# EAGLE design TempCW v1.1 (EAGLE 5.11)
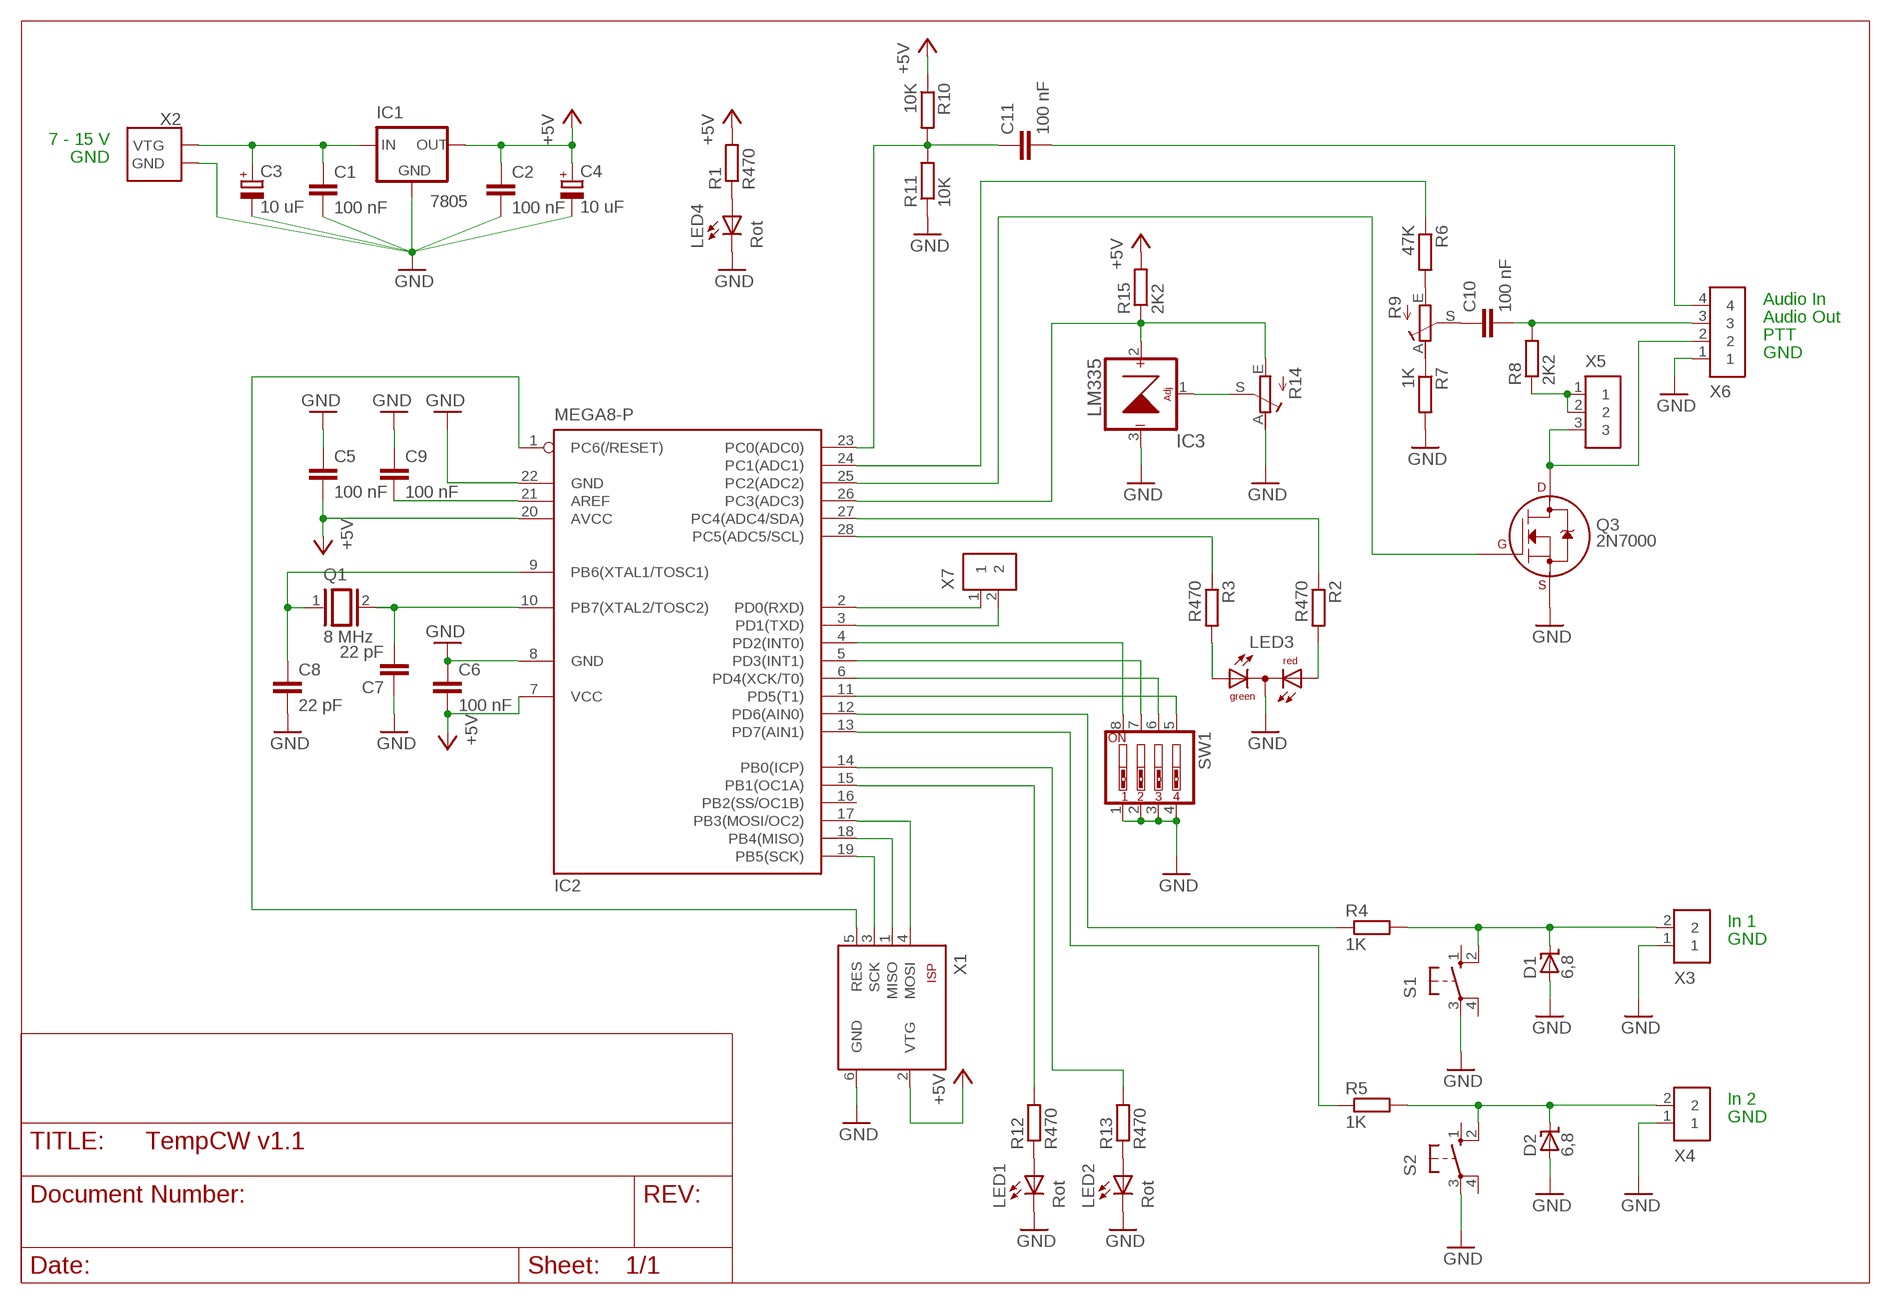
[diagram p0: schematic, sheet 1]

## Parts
C1  100 nF  CAPACITOR  [C]
C2  100 nF  CAPACITOR  [C]
C3  10 uF  CAPACITOR_POL6  [E2,5-6]
C4  10 uF  CAPACITOR_POL6  [E2,5-6]
C5  100 nF  CAPACITOR  [C]
C6  100 nF  CAPACITOR  [C]
C7  22 pF  CAPACITOR  [C]
C8  22 pF  CAPACITOR  [C]
C9  100 nF  CAPACITOR  [C]
C10  100 nF  CAPACITOR  [C]
C11  100 nF  CAPACITOR  [C]
D1  6,8  DIODE_SUPPRESSOR  [PRINT]
D2  6,8  DIODE_SUPPRESSOR  [PRINT]
IC1  7805  V-REG_B  [78XXS]
IC2  MEGA8-P  [DIL28-3]
IC3  LM335  [TO92-123]
LED1  Rot  LED_5MM  [5MM]
LED2  Rot  LED_5MM  [5MM]
LED3  Rot Grün  DUO_5  [DUO]
LED4  Rot  LED_5MM  [5MM]
Q1  8 MHz  CRYSTAL  [CRYSTAL]
Q3  2N7000  2N7000_TO92  [TO-92]
R1  R470  RESISTOR  [RESISTOR]
R2  R470  RESISTOR  [RESISTOR]
R3  R470  RESISTOR  [RESISTOR]
R4  1K  RESISTOR  [RESISTOR]
R5  1K  RESISTOR  [RESISTOR]
R6  47K  RESISTOR  [RESISTOR]
R7  1K  RESISTOR  [RESISTOR]
R8  2K2  RESISTOR  [RESISTOR]
R9  10K  TRIMM_SMALL  [RTRIM_SMALL]
R10  10K  RESISTOR  [RESISTOR]
R11  10K  RESISTOR  [RESISTOR]
R12  R470  RESISTOR  [RESISTOR]
R13  R470  RESISTOR  [RESISTOR]
R14  10K  TRIMM_SMALL  [RTRIM_SMALL]
R15  2K2  RESISTOR  [RESISTOR]
S1  S1  10-XX  [B3F-10XX]
S2  S2  10-XX  [B3F-10XX]
SW1  Dip4  DIP4  [DIP4]
X1  ISP  ISP_H6  [HARTING6]
X2  Power  POWER_W2  [WAGO2]
X3  2PIN  2PIN_W2  [WAGO2]
X4  2PIN  2PIN_W2  [WAGO2]
X5  3PIN  [PINHEAD_1X3]
X6  4PIN  4PIN_W4  [WAGO4]
X7  2PIN  [PINHEAD_1X2]

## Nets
+5V: C2.1 C4.+ C5.2 C6.2 IC1.OUT IC2.7(VCC) IC2.20(AVCC) R1.2 R10.1 R15.2 X1.2(VTG)
GND: C1.2 C2.2 C3.- C4.- C5.1 C6.1 C7.1 C8.2 C9.1 D1.A D2.A IC1.GND IC2.8(GND) IC2.22(GND) IC3.3(MINUS) LED1.K(C) LED2.K(C) LED3.K(C) LED4.K(C) Q3.1(S) R7.2 R11.1 R14.A S1.3(P) S2.3(P) SW1.1 SW1.2 SW1.3 SW1.4 X1.6(GND) X2.2(GND) X3.1 X4.1 X6.1
N$1: C8.1 IC2.9(PB6(XTAL1/TOSC1)) Q1.1
N$2: LED4.A R1.1
N$3: C7.2 IC2.10(PB7(XTAL2/TOSC2)) Q1.2
N$4: IC2.19(PB5(SCK)) X1.3(SCK)
N$5: C9.2 IC2.21(AREF)
N$6: IC2.18(PB4(MISO)) X1.1(MISO)
N$7: IC2.17(PB3(MOSI/OC2)) X1.4(MOSI)
N$8: IC2.1(PC6(/RESET)) X1.5(RES)
N$9: IC2.3(PD1(TXD)) X7.2
N$10: IC2.2(PD0(RXD)) X7.1
N$11: IC2.4(PD2(INT0)) SW1.8
N$12: IC2.5(PD3(INT1)) SW1.7
N$13: IC2.6(PD4(XCK/T0)) SW1.6
N$14: IC2.11(PD5(T1)) SW1.5
N$15: LED3.AR R2.2
N$16: LED3.AG R3.2
N$17: IC2.27(PC4(ADC4/SDA)) R2.1
N$18: IC2.28(PC5(ADC5/SCL)) R3.1
N$19: C1.1 C3.+ IC1.IN X2.1(VTG)
N$20: R6.2 R9.E
N$21: R7.1 R9.A
N$22: C10.2 R8.2 X6.3
N$23: R8.1 X5.1 X5.2
N$24: Q3.3(D) X5.3 X6.2
N$25: D1.C R4.2 S1.2(S1) X3.2
N$26: IC2.26(PC3(ADC3)) IC3.2(PLUS) R14.E R15.1
N$27: IC3.1(ADJ) R14.S
N$28: IC2.24(PC1(ADC1)) R6.1
N$29: IC2.25(PC2(ADC2)) Q3.2(G)
N$30: C11.1 IC2.23(PC0(ADC0)) R10.2 R11.2
N$32: C11.2 X6.4
N$33: D2.C R5.2 S2.2(S1) X4.2
N$34: LED1.A R12.1
N$35: LED2.A R13.1
N$36: IC2.15(PB1(OC1A)) R12.2
N$37: IC2.14(PB0(ICP)) R13.2
N$38: IC2.12(PD6(AIN0)) R4.1
N$39: IC2.13(PD7(AIN1)) R5.1
N$43: C10.1 R9.S
Unconnected: IC2.16(PB2(SS/OC1B)) S1.1(S) S1.4(P1) S2.1(S) S2.4(P1)

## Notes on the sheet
- 7 - 15 V
- GND
- Audio In
- Audio Out
- PTT
- GND
- In 1
- GND
- In 2
- GND

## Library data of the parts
C1 C2 C5-C11 = Capacitors:CAPACITOR: CAPACITOR, European symbol
C3 C4 = Capacitors:CAPACITOR_POL: POLARIZED CAPACITOR, European symbol
D1 D2 = Diodes:DIODE_SUPPRESSOR: Suppressor diode
IC1 = Voltage-Regulators:V-REG: VOLTAGE REGULATOR
IC2 = __atmel:MEGA8-P: MICROCONTROLLER 8 Kbytes FLASH, 1 kbytes SRAM, 512 bytes EEPROM, USART, 4-channel 10 bit ADC, 2-channel 8 bit ADC Pin compatible with Atmega48, ATMega88, ATMega168 Source: avr.lbr; OC_FARNELL: unknown; OC_NEWARK: unknown
IC3 = __lm335:LM335
LED1 LED2 LED4 = LEDs:LED: LED
LED3 = LEDs:DUO_5: DUO LED 2 colors, 5 mm, round
Q1 = Crystals:CRYSTAL: CRYSTAL
Q3 = __transistors:2N700*: 2N7000, 2N7002, NDS7002A N-channel enhancement mode MOSFET
R1-R8 R10-R13 R15 = Resistors:RESISTOR: RESISTOR, European symbol
R9 R14 = Resistors:TRIMM: Trimm resistor
S1 S2 = Switches:10-XX: OMRON SWITCH
SW1 = Switches:DIP4: DIP SWITCH
X1 = Connectors:ISP: HARTING
X2 = Connectors:POWER: WAGO SREW CLAMP
X3 X4 X7 = Connectors:2PIN
X5 = Connectors:3PIN
X6 = Connectors:4PIN

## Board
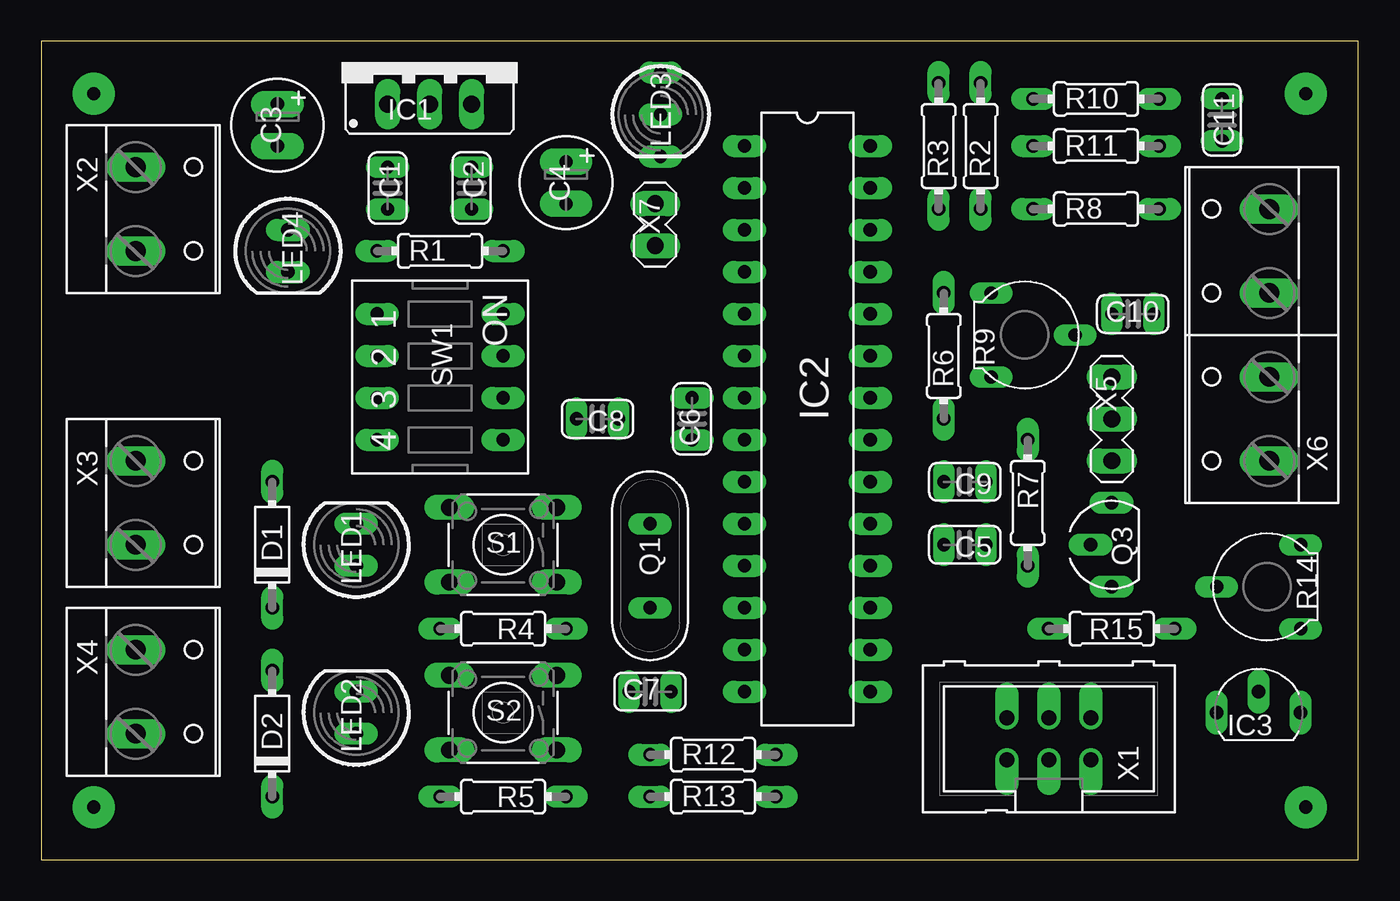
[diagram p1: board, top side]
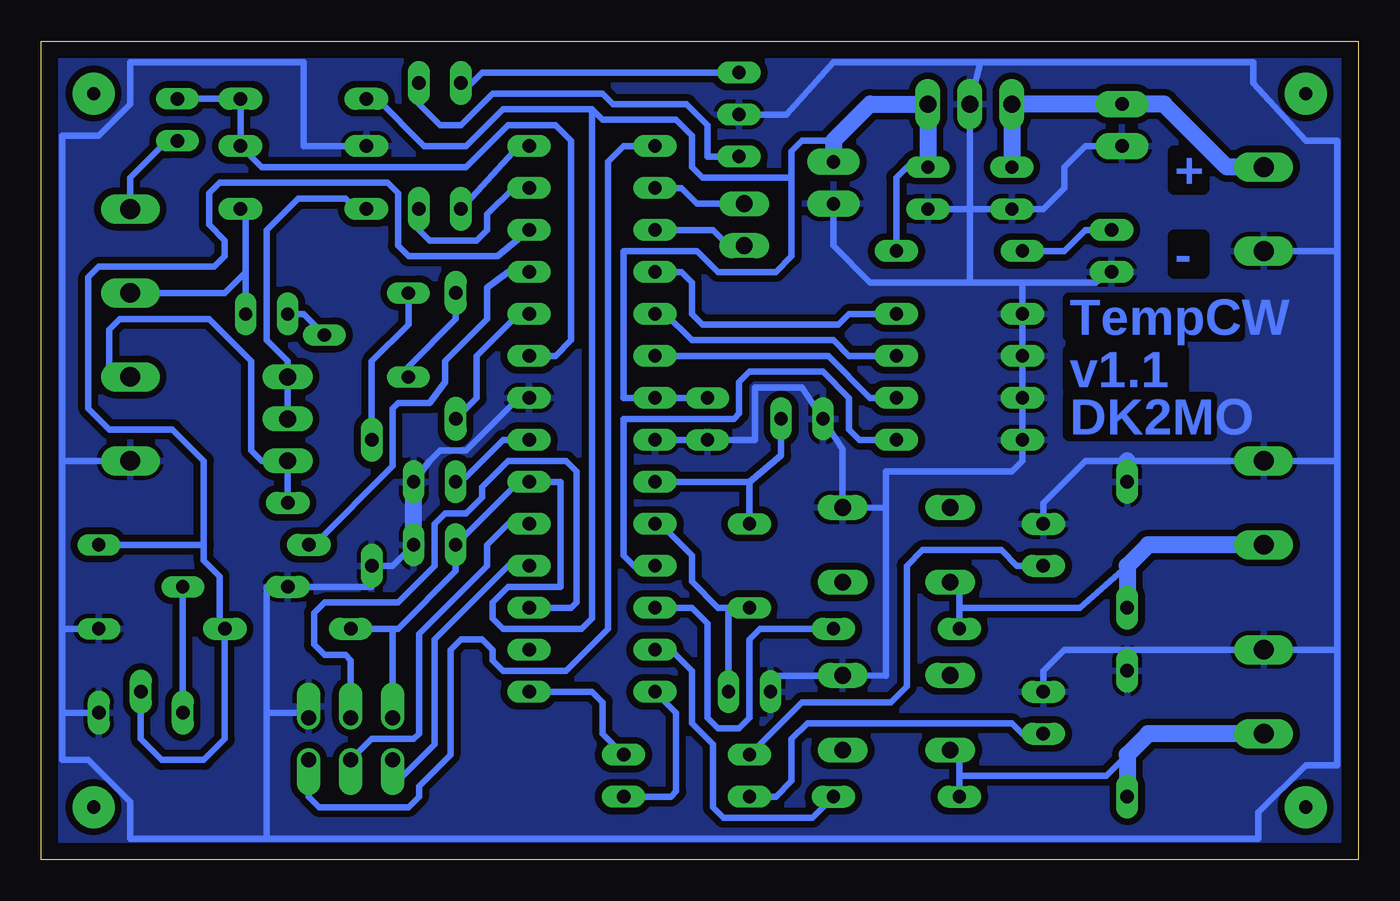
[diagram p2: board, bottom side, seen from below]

Size 79.68 x 49.52 mm. Coordinates in mm from the lower left corner, seen from the top.
Outline: 0,0 79.68,0 79.68,49.52 0,49.52 0,0
Copper layers (1*16): Top 0.035mm / dielectric 1.5mm / Bottom 0.035mm
Design rules "default": minimum track width 10mil, minimum drill 24mil, track to track 8mil, track to pad 8mil, pad to pad 8mil, via to via 8mil, smd to smd 8mil, copper to edge 40mil, drill to drill 8mil, minimum pad ring 10mil, minimum via ring 8mil, stop-mask expansion 4mil, vias tented up to drill 0mil, thermal gap 10mil

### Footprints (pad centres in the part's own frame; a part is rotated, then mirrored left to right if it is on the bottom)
C = drill 0.8 long: 1 -1.27,0; 2 1.27,0
E2,5-6 = drill 0.813 pad 1.6 long: + -1.27,0; - 1.27,0
PRINT = drill 0.813 long: A 3.81,0; C -3.81,0
78XXS = drill 1.016 long: GND 0,-2.54; IN -2.54,-2.54; OUT 2.54,-2.54
DIL28-3 = drill 0.813 long: 1 -16.51,-3.81; 2 -13.97,-3.81; 3 -11.43,-3.81; 4 -8.89,-3.81; 5 -6.35,-3.81; 6 -3.81,-3.81; 7 -1.27,-3.81; 8 1.27,-3.81; 9 3.81,-3.81; 10 6.35,-3.81; 11 8.89,-3.81; 12 11.43,-3.81; 13 13.97,-3.81; 14 16.51,-3.81; 15 16.51,3.81; 16 13.97,3.81; 17 11.43,3.81; 18 8.89,3.81; 19 6.35,3.81; 20 3.81,3.81; 21 1.27,3.81; 22 -1.27,3.81; 23 -3.81,3.81; 24 -6.35,3.81; 25 -8.89,3.81; 26 -11.43,3.81; 27 -13.97,3.81; 28 -16.51,3.81
TO92-123 = drill 0.813 long: 1 -2.54,0; 2 0,1.27; 3 2.54,0
5MM = drill 0.813 long: A -1.27,0; K 1.27,0
DUO = drill 0.813 long: AG -2.54,0; AR 2.54,0; K 0,0
CRYSTAL = drill 0.8 long: 1 -2.54,0; 2 2.54,0
TO-92 = drill 0.813 long: 1 -2.54,0; 2 0,1.27; 3 2.54,0
RESISTOR = drill 0.813 long: 1 -3.81,0; 2 3.81,0
RTRIM_SMALL = drill 0.8 long: A 2.54,0; E -2.54,0; S 0,-5.08
B3F-10XX = drill 1.016 long: 1 -3.251,2.261; 2 3.251,2.261; 3 -3.251,-2.261; 4 3.251,-2.261
DIP4 = drill 0.813 long: 1 -3.81,-3.81; 2 -1.27,-3.81; 3 1.27,-3.81; 4 3.81,-3.81; 5 3.81,3.81; 6 1.27,3.81; 7 -1.27,3.81; 8 -3.81,3.81
HARTING6 = drill 0.914 offset: 1 -2.54,-1.27; 2 -2.54,1.27; 3 0,-1.27; 4 0,1.27; 5 2.54,-1.27; 6 2.54,1.27
WAGO2 = drill 1.194 long: 1 -2.54,-0.635; 2 2.54,-0.635
PINHEAD_1X3 = drill 1.016 long: 1 -2.54,0; 2 0,0; 3 2.54,0
WAGO4 = drill 1.194 long: 1 -7.62,-0.635; 2 -2.54,-0.635; 3 2.54,-0.635; 4 7.62,-0.635
PINHEAD_1X2 = drill 1.016 long: 1 -1.27,0; 2 1.27,0

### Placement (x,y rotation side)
C1  20.95,40.64 270 top
C2  26.04,40.64 270 top
C3  14.29,44.45 270 top
C4  31.75,40.96 270 top
C5  55.88,19.05 180 top
C6  39.37,26.67 90 top
C7  36.83,10.16 0 top
C8  33.66,26.67 180 top
C9  55.88,22.86 180 top
C10  66.04,33.02 0 top
C11  71.44,44.77 270 top
D1  13.97,19.05 90 top
D2  13.97,7.62 90 top
IC1  23.5,48.26 0 top
IC2  46.35,26.67 270 top
IC3  73.66,8.89 0 top
LED1  19.05,19.05 90 top
LED2  19.05,8.89 90 top
LED3  37.47,45.09 270 top
LED4  14.92,36.83 270 top
Q1  36.83,17.78 270 top
Q3  64.77,19.05 90 top
R1  24.13,36.83 0 top
R2  56.83,43.18 90 top
R3  54.29,43.18 90 top
R4  27.94,13.97 180 top
R5  27.94,3.81 180 top
R6  54.61,30.48 90 top
R7  59.69,21.59 270 top
R8  63.82,39.37 0 top
R9  57.47,31.75 90 top
R10  63.82,46.04 0 top
R11  63.82,43.18 0 top
R12  40.64,6.35 0 top
R13  40.64,3.81 0 top
R14  76.2,16.51 270 top
R15  64.77,13.97 180 top
S1  27.94,19.05 180 top
S2  27.94,8.89 180 top
SW1  24.13,29.21 270 top
X1  60.96,7.3 0 top
X2  6.35,39.37 270 top
X3  6.35,21.59 270 top
X4  6.35,10.16 270 top
X5  64.77,26.67 270 top
X6  73.66,31.75 90 top
X7  37.15,38.42 270 top

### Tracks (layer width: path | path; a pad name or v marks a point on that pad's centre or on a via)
+5V
  Bottom 0.406: C6.2 IC2.7 44.45,27.94 44.45,36.83 40.01,36.83 38.73,35.56 35.24,35.56 34.29,36.51 34.29,41.27 | 58.42,13.97 X1.2 | 50.8,22.86 C5.2 54.61,17.46 58.1,13.97 58.42,13.97 | C2.1 27.3,41.91 27.94,41.27 R1.2 | R10.1 59.37,46.04 56.52,43.18 53.98,43.18 51.75,45.4 46.35,45.4 | 34.29,41.27 39.69,41.27 40.32,41.91 40.32,43.81 41.27,44.77 45.72,44.77 46.35,45.4 | IC2.20 48.26,22.86 48.26,16.51 51.44,16.51 52.39,15.56 52.39,14.61 51.75,13.97 46.99,13.97 46.35,14.61 46.35,45.4 | 58.42,13.97 R15.2 | 34.29,41.27 34.29,42.86 33.66,43.5 31.75,43.5
  Bottom 1.016: C2.1 IC1.OUT 29.53,45.72 31.75,43.5 C4.+ | IC2.20 50.8,22.86
GND
  Bottom 0.406: 23.5,39.37 C1.2 19.05,39.37 17.78,40.64 17.78,41.91 16.51,43.18 C3.- | 23.5,39.37 C2.2 | 1.27,36.83 X2.2 | 1.27,24.13 1.27,36.83 | 1.27,24.13 X3.1 13.97,24.13 16.51,24.13 19.05,21.59 LED1.K | 1.27,12.7 1.27,24.13 | 1.27,12.7 X4.1 13.97,12.7 | 78.42,24.13 X6.1 | 23.5,39.37 IC1.GND 22.86,48.26 | 66.04,8.89 63.5,8.89 X1.6 | 66.04,1.27 66.04,8.89 | 35.56,10.79 35.24,11.11 31.11,11.11 S2.3 28.57,11.11 28.57,21.27 | 13.97,12.7 D2.A | 13.97,12.7 17.78,12.7 19.05,11.43 LED2.K | IC2.8 C6.1 36.51,25.4 36.51,28.57 33.66,28.57 C8.2 31.19,24.84 S1.3 28.57,21.27 | 78.42,13.97 78.42,24.13 | R11.1 63.82,43.18 63.82,48.26 74.3,48.26 74.3,45.72 76.2,43.81 78.42,43.81 78.42,24.13 | C4.- 31.75,37.15 29.53,34.92 23.5,34.92 | 23.5,39.37 23.5,34.92 | 23.5,34.92 20.32,34.92 | 28.57,21.27 28.57,23.5 20.95,23.5 20.32,24.13 SW1.4 SW1.3 SW1.2 SW1.1 20.32,34.92 | IC2.22 50.8,27.94 53.98,24.77 55.56,24.77 56.2,24.13 C9.1 | 66.04,8.89 66.04,16.51 Q3.1 59.69,16.51 R7.2 58.42,17.78 C5.1 | 78.42,13.97 R14.A | 1.27,36.83 1.27,43.5 3.17,43.5 6.35,46.99 6.35,48.26 22.86,48.26 | 1.27,12.7 1.27,5.71 3.17,5.71 6.03,2.86 6.03,1.27 66.04,1.27 | 66.04,1.27 74.3,1.27 74.3,3.49 76.83,6.03 78.42,6.03 78.42,8.89 | 78.42,8.89 78.42,13.97 | LED4.K 15.88,34.92 20.32,34.92 | 78.42,8.89 IC3.3 | LED3.K 34.61,45.09 31.75,48.26 22.86,48.26
  Bottom 1.016: C5.1 C9.1 | 35.56,10.79 C7.1 | 13.97,24.13 D1.A
  pour Bottom (isolate 0.406): 0,49.53 79.69,49.53 79.69,0 0,0
N$1
  Bottom 0.406: 36.83,22.86 IC2.9 | Q1.1 36.83,22.86 | C8.1 34.92,24.45 36.83,22.86
N$2
  Bottom 0.406: LED4.A 16.51,38.1 17.78,36.83 R1.1
N$3
  Bottom 0.406: C7.2 38.1,15.24 | 38.1,15.24 Q1.2 | 38.1,15.24 38.73,15.24 40.32,16.83 40.32,18.41 41.91,20 42.23,20 IC2.10
N$4
  Bottom 0.406: IC2.19 51.44,20.32 52.7,19.05 52.7,17.78 56.83,13.65 56.83,7.62 57.15,7.3 59.69,7.3 X1.3
N$5
  Bottom 0.406: IC2.21 51.75,25.4 54.29,22.86 C9.2
N$6
  Bottom 0.406: IC2.18 51.44,17.78 55.88,13.34 55.88,6.99 58.42,4.45 X1.1
N$7
  Bottom 0.406: IC2.17 47.62,15.24 47.31,15.56 47.31,23.5 47.94,24.13 51.44,24.13 53.02,22.54 53.02,21.91 53.98,20.95 55.24,20.95 55.88,20.32 55.88,17.78 58.1,15.56 62.55,15.56 63.18,14.92 63.18,13.02 62.55,12.38 61.28,12.38 60.96,12.06 X1.4
N$8
  Bottom 0.406: IC2.1 44.45,43.18 45.4,42.23 45.4,13.97 47.94,11.43 51.75,11.43 52.39,12.06 52.39,12.7 53.02,13.34 54.29,13.34 54.93,12.7 54.93,6.35 56.83,4.45 56.83,3.81 57.47,3.17 62.87,3.17 63.5,3.81 X1.5
N$9
  Bottom 0.406: IC2.3 39.05,38.1 38.1,37.15 X7.2
N$10
  Bottom 0.406: IC2.2 40.96,40.64 40.01,39.69 X7.1
N$11
  Bottom 0.406: IC2.4 40.96,35.56 40.32,34.92 40.32,33.02 39.69,32.38 31.43,32.38 30.8,33.02 SW1.8
N$12
  Bottom 0.406: SW1.7 30.8,30.48 31.75,31.43 40.32,31.43 41.91,33.02 IC2.5
N$13
  Bottom 0.406: SW1.6 29.53,27.94 32.07,30.48 IC2.6
N$14
  Bottom 0.406: IC2.11 43.81,17.78 44.45,18.41 44.45,26.67 37.78,26.67 37.47,26.99 37.47,28.89 36.83,29.53 32.38,29.53 30.8,27.94 30.8,26.04 30.16,25.4 SW1.5
N$15
  Bottom 0.406: R2.2 56.83,45.72 55.56,44.45 54.29,44.45 52.39,46.35 45.72,46.35 45.09,45.72 40.64,45.72 39.37,44.45 39.37,42.55 LED3.AR
N$16
  Bottom 0.406: R3.2 53.66,46.99 53.02,47.62 LED3.AG
N$17
  Bottom 0.406: IC2.27 51.12,40.64 52.7,39.05 52.7,38.1 53.34,37.47 56.2,37.47 56.83,38.1 R2.1
N$18
  Bottom 0.406: R3.1 50.8,43.18 IC2.28
N$19
  Bottom 1.016: X2.1 7.94,41.91 11.75,45.72 C3.+ IC1.IN C1.1
N$20
  Bottom 0.406: R6.2 54.61,32.7 57.47,29.84 R9.E
N$21
  Bottom 0.406: R9.A 57.47,32.38 59.69,30.16 R7.1
N$22
  Bottom 0.406: R8.2 67.31,39.37 67.31,35.56 | C10.2 67.31,35.56 | X6.3 68.58,34.29 67.31,35.56
N$23
  Bottom 0.406: X5.2 X5.1 64.77,30.16 66.04,31.43 66.04,38.1 64.14,40.01 61.28,40.01 60.64,39.37 R8.1
N$24
  Bottom 0.406: Q3.3 X5.3 66.36,24.13 66.99,24.77 66.99,30.16 69.53,32.7 74.93,32.7 75.56,32.07 75.56,29.53 74.61,29.53 X6.2
N$25
  Bottom 0.406: 13.97,17.78 16.83,15.24 24.13,15.24 R4.2 24.13,16.83 24.17,16.79 S1.2
  Bottom 1.016: X3.2 12.7,19.05 13.97,17.78 D1.C
N$26
  Bottom 0.406: 69.85,19.05 R14.E | IC2.26 52.07,36.51 57.47,36.51 58.1,37.15 58.1,40.32 58.74,40.96 68.9,40.96 69.53,40.32 69.53,38.42 68.58,37.47 68.58,36.51 69.22,35.88 76.2,35.88 76.83,35.24 76.83,27.3 75.56,26.04 71.75,26.04 69.85,24.13 69.85,19.05 | IC3.2 73.66,7.3 72.39,6.03 69.85,6.03 68.58,7.3 R15.1 68.9,14.29 68.9,17.14 69.85,18.1 69.85,19.05
N$27
  Bottom 0.406: IC3.1 R14.S
N$28
  Bottom 0.406: R6.1 53.34,27.94 53.34,30.48 50.8,33.02 IC2.24
N$29
  Bottom 0.406: IC2.25 51.44,35.56 52.7,34.61 52.7,32.7 55.24,30.16 55.24,28.89 56.2,27.62 58.1,27.62 58.42,27.3 58.42,23.81 63.18,19.05 Q3.2
N$30
  Bottom 0.406: C11.1 R10.2 R11.2 66.36,41.91 53.98,41.91 51.44,44.45 48.58,44.45 47.62,43.5 47.62,31.43 48.58,30.48 IC2.23
N$31  (via drill 0.8 pad 2.54)
  other vias: 3.17,46.35
N$32
  Bottom 0.406: C11.2 72.07,43.5 72.39,43.18 74.3,41.27 X6.4 74.93,39.37
N$33
  Bottom 0.406: 24.13,5.08 24.13,6.35 S2.2 | 13.97,6.35 15.24,5.08 24.13,5.08 | 24.13,5.08 R5.2
  Bottom 1.016: X4.2 12.7,7.62 13.97,6.35 D2.C
N$34
  Bottom 0.406: LED1.A 20.64,17.78 21.59,18.73 26.35,18.73 27.3,17.78 27.3,10.48 28.26,9.53 33.66,9.53 R12.1
N$35
  Bottom 0.406: LED2.A 20.32,7.62 20.95,8.26 33.34,8.26 34.29,7.3 34.29,4.76 35.24,3.81 R13.1
N$36
  Bottom 0.406: R12.2 45.72,7.62 45.72,9.53 46.35,10.16 IC2.15
N$37
  Bottom 0.406: IC2.14 41.27,8.89 41.27,4.13 41.59,3.81 R13.2
N$38
  Bottom 0.406: R4.1 36.2,13.97 36.83,13.34 36.83,8.57 37.47,7.94 38.73,7.94 39.37,8.57 39.37,14.29 40.32,15.24 IC2.12
N$39
  Bottom 0.406: R5.1 33.02,2.54 38.42,2.54 39.05,3.17 39.05,6.99 40.32,8.26 40.32,11.43 41.59,12.7 IC2.13
N$40  (via drill 0.8 pad 2.54)
  other vias: 76.52,46.35
N$41  (via drill 0.8 pad 2.54)
  other vias: 76.52,3.17
N$42  (via drill 0.8 pad 2.54)
  other vias: 3.17,3.17
N$43
  Bottom 0.406: R9.S 63.82,33.02 C10.1

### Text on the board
Bottom: + | - | TempCW | v1.1 | DK2MO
